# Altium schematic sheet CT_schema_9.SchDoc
size 144 x 119 mm
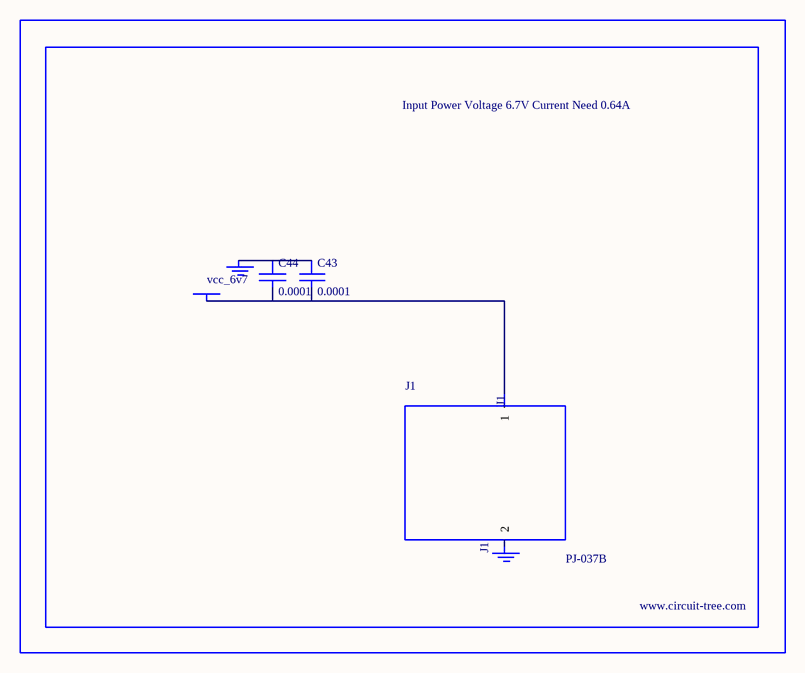
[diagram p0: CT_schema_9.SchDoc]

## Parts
BORDER8  (no value)
C43  0.0001  [EXV-9H]
C44  0.0001  [EXV-9H]
GND_INSTANCE_8_0  (no value)
GND_INSTANCE_8_1  (no value)
J1  PJ-037B  [PJ-037B_PACKAGE]
POWER_INSTANCE_8_0  vcc_6v7

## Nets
NetC43_1: C43.1 C44.1 GND_INSTANCE_8_0.0(GND)
NetC43_2: C43.2 C44.2 J1.1 POWER_INSTANCE_8_0.0(PWR)

Not connected (* = marked no-connect by the designer): GND_INSTANCE_8_1 0(GND); J1 2

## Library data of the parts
BORDER8 = BORDER_PAGE8
C43 C44 = EDK107M035A9HAA
GND_INSTANCE_8_0 GND_INSTANCE_8_1 = GND
POWER_INSTANCE_8_0 = PWR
